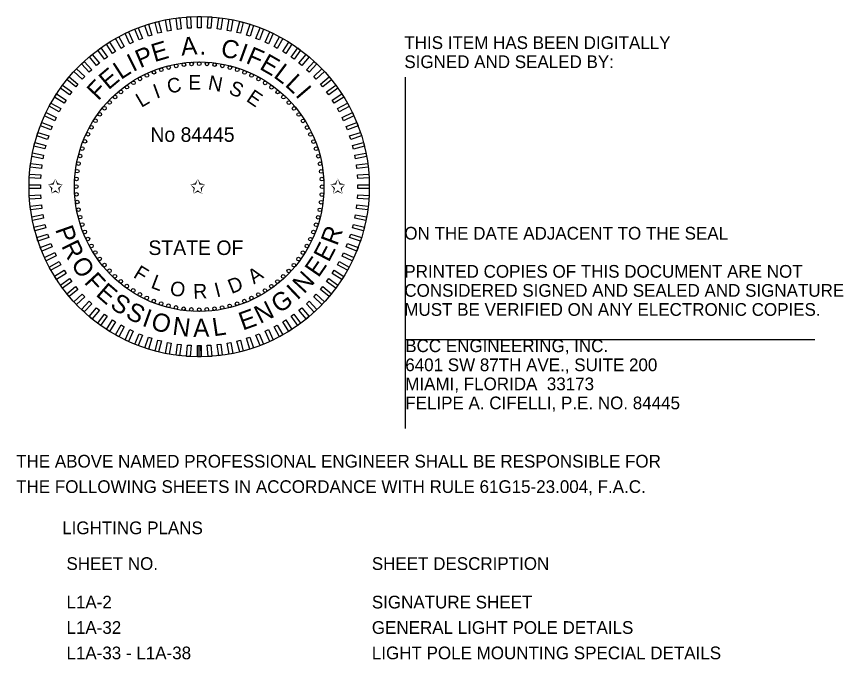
# Model space of a CAD drawing. Extents: x -811.2 to -795.1, y -2238.2 to -2204.
# Drawn here: x -802.539 to -797.983, y -2208.297 to -2204.755 of the extents above; entities that cross this region are included whole.
import ezdxf

# ---------------------------------------------------------------- set-up
doc = ezdxf.new("R2010")
doc.units = 0
for name, color, linetype in [('AdhocPoint_dp', 7, 'Continuous'), ('PlotBorder_dp', 7, 'Continuous'), ('TextMinor', 7, 'Continuous'), ('TextMisc', 7, 'Continuous'), ('TextShtNo', 7, 'Continuous')]:
    doc.layers.add(name, color=color, linetype=linetype)

msp = doc.modelspace()

# ---------------------------------------------------------------- linework, layer by layer
at = {"layer": 'AdhocPoint_dp'}
for p, q in [((-800.3974, -2205.0892), (-800.3974, -2207.0239)), ((-800.3974, -2206.5339), (-798.1407, -2206.5339))]:
    msp.add_line(p, q, dxfattribs=at)
at = {"layer": 'TextMinor'}
for radius in [0.9375, 0.6875]:
    msp.add_circle((-801.5329, -2205.6926), radius, dxfattribs=at)
at = {"layer": 'TextShtNo'}
for p, q in [((-801.5429, -2206.6301), (-801.5431, -2206.5676)), ((-801.5329, -2206.6301), (-801.5331, -2206.5676)), ((-801.5229, -2206.6301), (-801.5231, -2206.5676))]:
    msp.add_line(p, q, dxfattribs=at)
for points in [[(-801.7407, -2204.8425), (-801.7602, -2204.8475), (-801.7758, -2204.7871), (-801.7562, -2204.782)], [(-801.6869, -2204.8312), (-801.7067, -2204.8349), (-801.7184, -2204.7736), (-801.6986, -2204.7698)], [(-801.6325, -2204.8232), (-801.6525, -2204.8257), (-801.6603, -2204.7638), (-801.6403, -2204.7612)], [(-801.5777, -2204.8187), (-801.5978, -2204.8199), (-801.6018, -2204.7576), (-801.5816, -2204.7563)], [(-801.5227, -2204.8176), (-801.5429, -2204.8176), (-801.5429, -2204.7551), (-801.5227, -2204.7551)], [(-801.4678, -2204.8199), (-801.488, -2204.8187), (-801.484, -2204.7563), (-801.4639, -2204.7576)], [(-801.4131, -2204.8257), (-801.4332, -2204.8232), (-801.4254, -2204.7613), (-801.4053, -2204.7638)], [(-801.359, -2204.835), (-801.3788, -2204.8312), (-801.3671, -2204.7699), (-801.3473, -2204.7736)], [(-801.3054, -2204.8476), (-801.325, -2204.8426), (-801.3095, -2204.7821), (-801.2899, -2204.7871)], [(-801.8456, -2204.8753), (-801.8643, -2204.8827), (-801.8873, -2204.8246), (-801.8686, -2204.8172)], [(-801.7936, -2204.8572), (-801.8128, -2204.8635), (-801.8321, -2204.8041), (-801.8129, -2204.7979)], [(-801.2528, -2204.8635), (-801.272, -2204.8573), (-801.2527, -2204.7979), (-801.2335, -2204.8042)], [(-801.2013, -2204.8828), (-801.2201, -2204.8753), (-801.1971, -2204.8173), (-801.1783, -2204.8247)], [(-801.9455, -2204.9209), (-801.9632, -2204.9306), (-801.9933, -2204.8759), (-801.9756, -2204.8662)], [(-801.8963, -2204.8965), (-801.9145, -2204.9051), (-801.9411, -2204.8486), (-801.9229, -2204.84)], [(-801.1511, -2204.9052), (-801.1694, -2204.8966), (-801.1428, -2204.8401), (-801.1246, -2204.8487)], [(-801.1025, -2204.9307), (-801.1201, -2204.921), (-801.0901, -2204.8663), (-801.0724, -2204.876)], [(-802.039, -2204.9787), (-802.0553, -2204.9906), (-802.092, -2204.94), (-802.0757, -2204.9282)], [(-801.9932, -2204.9483), (-802.0102, -2204.9591), (-802.0437, -2204.9064), (-802.0266, -2204.8956)], [(-801.0555, -2204.9592), (-801.0725, -2204.9484), (-801.039, -2204.8957), (-801.022, -2204.9065)], [(-801.0104, -2204.9907), (-801.0267, -2204.9788), (-800.99, -2204.9283), (-800.9737, -2204.9402)], [(-802.0828, -2205.0119), (-802.0984, -2205.0247), (-802.1382, -2204.9766), (-802.1226, -2204.9638)], [(-800.9673, -2205.0249), (-800.9829, -2205.012), (-800.9431, -2204.9639), (-800.9275, -2204.9768)], [(-802.1245, -2205.0478), (-802.1392, -2205.0616), (-802.182, -2205.0161), (-802.1672, -2205.0022)], [(-800.9265, -2205.0617), (-800.9412, -2205.0479), (-800.8985, -2205.0024), (-800.8838, -2205.0162)], [(-802.1638, -2205.0862), (-802.1776, -2205.1009), (-802.2232, -2205.0581), (-802.2093, -2205.0434)], [(-800.8881, -2205.101), (-800.9019, -2205.0863), (-800.8564, -2205.0436), (-800.8426, -2205.0583)], [(-802.2007, -2205.127), (-802.2135, -2205.1425), (-802.2616, -2205.1027), (-802.2488, -2205.0872)], [(-800.8522, -2205.1427), (-800.8651, -2205.1271), (-800.817, -2205.0873), (-800.8041, -2205.1029)], [(-802.2349, -2205.17), (-802.2467, -2205.1864), (-802.2972, -2205.1497), (-802.2854, -2205.1333)], [(-800.819, -2205.1865), (-800.8309, -2205.1702), (-800.7804, -2205.1335), (-800.7685, -2205.1498)], [(-802.2663, -2205.2151), (-802.2771, -2205.2322), (-802.3298, -2205.1987), (-802.319, -2205.1817)], [(-800.7887, -2205.2323), (-800.7995, -2205.2153), (-800.7468, -2205.1818), (-800.7359, -2205.1989)], [(-802.2948, -2205.2621), (-802.3045, -2205.2798), (-802.3593, -2205.2497), (-802.3495, -2205.232)], [(-800.7612, -2205.28), (-800.7709, -2205.2623), (-800.7162, -2205.2322), (-800.7065, -2205.2499)], [(-802.3203, -2205.3108), (-802.3289, -2205.3291), (-802.3854, -2205.3025), (-802.3768, -2205.2842)], [(-800.7368, -2205.3292), (-800.7454, -2205.311), (-800.6889, -2205.2844), (-800.6803, -2205.3027)], [(-802.3428, -2205.361), (-802.3502, -2205.3798), (-802.4082, -2205.3568), (-802.4008, -2205.338)], [(-800.7156, -2205.3799), (-800.723, -2205.3612), (-800.665, -2205.3382), (-800.6575, -2205.357)], [(-802.362, -2205.4125), (-802.3682, -2205.4317), (-802.4276, -2205.4124), (-802.4214, -2205.3932)], [(-800.6976, -2205.4319), (-800.7038, -2205.4127), (-800.6444, -2205.3934), (-800.6382, -2205.4126)], [(-802.3779, -2205.4651), (-802.383, -2205.4847), (-802.4434, -2205.4691), (-802.4384, -2205.4496)], [(-800.6829, -2205.4849), (-800.6879, -2205.4653), (-800.6274, -2205.4498), (-800.6224, -2205.4693)], [(-802.3905, -2205.5186), (-802.3943, -2205.5385), (-802.4557, -2205.5268), (-802.4519, -2205.5069)], [(-800.6715, -2205.5386), (-800.6753, -2205.5188), (-800.6139, -2205.5071), (-800.6102, -2205.5269)], [(-802.3998, -2205.5728), (-802.4023, -2205.5928), (-802.4643, -2205.585), (-802.4617, -2205.565)], [(-800.6635, -2205.593), (-800.666, -2205.573), (-800.6041, -2205.5652), (-800.6016, -2205.5852)], [(-802.4056, -2205.6275), (-802.4069, -2205.6476), (-802.4692, -2205.6437), (-802.4679, -2205.6236)], [(-800.659, -2205.6478), (-800.6603, -2205.6277), (-800.5979, -2205.6238), (-800.5967, -2205.6439)], [(-802.408, -2205.6824), (-802.408, -2205.7026), (-802.4704, -2205.7026), (-802.4704, -2205.6824)], [(-800.6579, -2205.7028), (-800.6579, -2205.6826), (-800.5955, -2205.6826), (-800.5955, -2205.7028)], [(-802.4069, -2205.7374), (-802.4056, -2205.7575), (-802.4679, -2205.7614), (-802.4692, -2205.7413)], [(-800.6603, -2205.7577), (-800.659, -2205.7376), (-800.5967, -2205.7415), (-800.5979, -2205.7616)], [(-802.4023, -2205.7922), (-802.3998, -2205.8122), (-802.4618, -2205.82), (-802.4643, -2205.8)], [(-800.6661, -2205.8124), (-800.6635, -2205.7923), (-800.6016, -2205.8002), (-800.6041, -2205.8202)], [(-802.3944, -2205.8466), (-802.3906, -2205.8664), (-802.4519, -2205.8781), (-802.4557, -2205.8583)], [(-800.6753, -2205.8666), (-800.6715, -2205.8467), (-800.6102, -2205.8584), (-800.614, -2205.8783)], [(-802.383, -2205.9003), (-802.378, -2205.9199), (-802.4385, -2205.9354), (-802.4435, -2205.9159)], [(-800.6879, -2205.9201), (-800.6829, -2205.9005), (-800.6224, -2205.916), (-800.6274, -2205.9356)], [(-802.3683, -2205.9533), (-802.362, -2205.9725), (-802.4214, -2205.9918), (-802.4277, -2205.9726)], [(-800.7039, -2205.9727), (-800.6976, -2205.9535), (-800.6382, -2205.9728), (-800.6445, -2205.992)], [(-802.3503, -2206.0052), (-802.3428, -2206.024), (-802.4009, -2206.047), (-802.4083, -2206.0282)], [(-800.7231, -2206.0242), (-800.7157, -2206.0054), (-800.6576, -2206.0284), (-800.665, -2206.0472)], [(-802.329, -2206.0559), (-802.3204, -2206.0742), (-802.3769, -2206.1008), (-802.3855, -2206.0825)], [(-800.7455, -2206.0744), (-800.7369, -2206.0561), (-800.6804, -2206.0827), (-800.689, -2206.101)], [(-802.3046, -2206.1052), (-802.2949, -2206.1229), (-802.3496, -2206.153), (-802.3593, -2206.1353)], [(-800.771, -2206.1231), (-800.7613, -2206.1054), (-800.7066, -2206.1355), (-800.7163, -2206.1532)], [(-802.2772, -2206.1529), (-802.2664, -2206.1699), (-802.3191, -2206.2034), (-802.3299, -2206.1863)], [(-800.7996, -2206.1701), (-800.7888, -2206.153), (-800.736, -2206.1865), (-800.7469, -2206.2035)], [(-802.2468, -2206.1987), (-802.235, -2206.215), (-802.2855, -2206.2517), (-802.2973, -2206.2354)], [(-800.831, -2206.2152), (-800.8191, -2206.1988), (-800.7686, -2206.2355), (-800.7805, -2206.2519)], [(-802.2136, -2206.2425), (-802.2008, -2206.2581), (-802.2489, -2206.2979), (-802.2618, -2206.2823)], [(-800.8652, -2206.2582), (-800.8523, -2206.2427), (-800.8042, -2206.2825), (-800.8171, -2206.298)], [(-802.1778, -2206.2842), (-802.1639, -2206.2989), (-802.2095, -2206.3416), (-802.2233, -2206.3269)], [(-800.902, -2206.299), (-800.8882, -2206.2843), (-800.8427, -2206.327), (-800.8565, -2206.3418)], [(-802.1394, -2206.3235), (-802.1246, -2206.3373), (-802.1674, -2206.3828), (-802.1821, -2206.369)], [(-800.9414, -2206.3374), (-800.9266, -2206.3236), (-800.8839, -2206.3691), (-800.8986, -2206.383)], [(-802.0985, -2206.3603), (-802.083, -2206.3732), (-802.1228, -2206.4213), (-802.1383, -2206.4084)], [(-800.983, -2206.3733), (-800.9675, -2206.3604), (-800.9277, -2206.4086), (-800.9432, -2206.4214)], [(-802.0555, -2206.3945), (-802.0392, -2206.4064), (-802.0759, -2206.4569), (-802.0922, -2206.445)], [(-802.0104, -2206.426), (-801.9933, -2206.4368), (-802.0268, -2206.4895), (-802.0438, -2206.4787)], [(-801.0727, -2206.4369), (-801.0556, -2206.4261), (-801.0222, -2206.4788), (-801.0392, -2206.4896)], [(-801.0268, -2206.4065), (-801.0105, -2206.3946), (-800.9738, -2206.4451), (-800.9901, -2206.457)], [(-801.9634, -2206.4545), (-801.9457, -2206.4642), (-801.9758, -2206.5189), (-801.9935, -2206.5092)], [(-801.1203, -2206.4643), (-801.1026, -2206.4546), (-801.0725, -2206.5093), (-801.0902, -2206.519)], [(-801.9147, -2206.48), (-801.8964, -2206.4886), (-801.923, -2206.5451), (-801.9413, -2206.5365)], [(-801.8645, -2206.5024), (-801.8457, -2206.5099), (-801.8687, -2206.5679), (-801.8875, -2206.5605)], [(-801.813, -2206.5217), (-801.7938, -2206.5279), (-801.8131, -2206.5873), (-801.8323, -2206.581)], [(-801.2722, -2206.5279), (-801.253, -2206.5217), (-801.2337, -2206.5811), (-801.2529, -2206.5873)], [(-801.2203, -2206.5099), (-801.2015, -2206.5025), (-801.1785, -2206.5606), (-801.1973, -2206.568)], [(-801.1696, -2206.4887), (-801.1513, -2206.4801), (-801.1247, -2206.5366), (-801.143, -2206.5452)], [(-801.7604, -2206.5376), (-801.7409, -2206.5426), (-801.7564, -2206.6031), (-801.7759, -2206.5981)], [(-801.7069, -2206.5502), (-801.6871, -2206.554), (-801.6988, -2206.6153), (-801.7186, -2206.6116)], [(-801.6527, -2206.5594), (-801.6327, -2206.562), (-801.6405, -2206.6239), (-801.6605, -2206.6214)], [(-801.598, -2206.5653), (-801.5779, -2206.5665), (-801.5818, -2206.6288), (-801.602, -2206.6276)], [(-801.5431, -2206.5676), (-801.5229, -2206.5676), (-801.5229, -2206.6301), (-801.5431, -2206.6301)], [(-801.4881, -2206.5665), (-801.468, -2206.5653), (-801.4641, -2206.6276), (-801.4842, -2206.6289)], [(-801.4334, -2206.562), (-801.4133, -2206.5595), (-801.4055, -2206.6214), (-801.4255, -2206.624)], [(-801.379, -2206.554), (-801.3591, -2206.5503), (-801.3474, -2206.6116), (-801.3673, -2206.6154)], [(-801.3252, -2206.5427), (-801.3056, -2206.5376), (-801.2901, -2206.5981), (-801.3097, -2206.6031)]]:
    msp.add_lwpolyline(points, close=True, dxfattribs=at)
for centre in [(-801.6593, -2205.027), (-801.6173, -2205.0204), (-801.5749, -2205.0164), (-801.5324, -2205.0151), (-801.4898, -2205.0165), (-801.4475, -2205.0205), (-801.4054, -2205.0272), (-801.7818, -2205.0625), (-801.7417, -2205.0481), (-801.7009, -2205.0363), (-801.3639, -2205.0366), (-801.323, -2205.0485), (-801.283, -2205.0629), (-801.8955, -2205.1203), (-801.8588, -2205.0987), (-801.8209, -2205.0794), (-801.244, -2205.0798), (-801.2061, -2205.0992), (-801.1694, -2205.1209), (-801.9307, -2205.1442), (-801.1343, -2205.1448), (-801.9963, -2205.1984), (-801.9643, -2205.1702), (-801.1007, -2205.171), (-801.0688, -2205.1991), (-802.0264, -2205.2284), (-801.0387, -2205.2292), (-802.0807, -2205.2939), (-802.0546, -2205.2603), (-801.0106, -2205.2612), (-800.9845, -2205.2948), (-802.1046, -2205.3291), (-800.9606, -2205.3301), (-802.1263, -2205.3657), (-800.939, -2205.3667), (-802.1457, -2205.4036), (-800.9197, -2205.4047), (-802.1771, -2205.4827), (-802.1626, -2205.4427), (-800.9028, -2205.4437), (-800.8884, -2205.4838), (-802.189, -2205.5236), (-800.8766, -2205.5247), (-802.1983, -2205.5651), (-800.8674, -2205.5662), (-802.205, -2205.6071), (-800.8607, -2205.6082), (-802.209, -2205.6495), (-800.8568, -2205.6506), (-802.2104, -2205.692), (-800.8555, -2205.6932), (-802.2091, -2205.7346), (-800.8568, -2205.7357), (-802.2051, -2205.7769), (-800.8609, -2205.7781), (-802.1985, -2205.819), (-800.8676, -2205.8201), (-802.1893, -2205.8605), (-800.8769, -2205.8616), (-802.1774, -2205.9014), (-802.163, -2205.9415), (-800.8888, -2205.9025), (-802.1462, -2205.9805), (-800.9202, -2205.9816), (-800.9032, -2205.9425), (-802.1269, -2206.0185), (-800.9395, -2206.0195), (-802.1052, -2206.0551), (-800.9612, -2206.0561), (-802.0813, -2206.0903), (-802.0553, -2206.124), (-800.9852, -2206.0913), (-802.0272, -2206.1559), (-801.0395, -2206.1568), (-801.0113, -2206.1249), (-801.9971, -2206.1861), (-801.9652, -2206.2142), (-801.1015, -2206.215), (-801.0696, -2206.1868), (-801.9316, -2206.2403), (-801.1352, -2206.241), (-801.8964, -2206.2643), (-801.8598, -2206.286), (-801.8219, -2206.3053), (-801.245, -2206.3058), (-801.207, -2206.2865), (-801.1704, -2206.2649), (-801.7828, -2206.3223), (-801.7428, -2206.3367), (-801.702, -2206.3486), (-801.365, -2206.3489), (-801.3241, -2206.3371), (-801.2841, -2206.3227), (-801.6604, -2206.358), (-801.6184, -2206.3647), (-801.576, -2206.3687), (-801.5329, -2206.3701), (-801.4909, -2206.3688), (-801.4486, -2206.3648), (-801.4065, -2206.3582)]:
    msp.add_circle(centre, 0.01, dxfattribs=at)

# ---------------------------------------------------------------- texts
at = {"layer": 'PlotBorder_dp'}
for s, p in [('THIS ITEM HAS BEEN DIGITALLY', (-800.4024, -2204.934)), ('SIGNED AND SEALED BY:', (-800.4024, -2205.039)), ('ON THE DATE ADJACENT TO THE SEAL', (-800.4024, -2205.984)), ('PRINTED COPIES OF THIS DOCUMENT ARE NOT ', (-800.4024, -2206.194)), ('CONSIDERED SIGNED AND SEALED AND SIGNATURE ', (-800.4024, -2206.299)), ('MUST BE VERIFIED ON ANY ELECTRONIC COPIES.', (-800.4024, -2206.404)), ('BCC ENGINEERING, INC.', (-800.3974, -2206.6039)), ('6401 SW 87TH AVE., SUITE 200', (-800.3974, -2206.7089)), ('MIAMI, FLORIDA  33173', (-800.3974, -2206.8139)), ('FELIPE A. CIFELLI, P.E. NO. 84445', (-800.3974, -2206.9189)), ('THE ABOVE NAMED PROFESSIONAL ENGINEER SHALL BE RESPONSIBLE FOR ', (-802.5415, -2207.24)), ('THE FOLLOWING SHEETS IN ACCORDANCE WITH RULE 61G15-23.004, F.A.C.', (-802.5415, -2207.38)), ('LIGHTING PLANS', (-802.2878, -2207.6071))]:
    msp.add_text(s, height=0.07, dxfattribs=at).set_placement(p)
at = {"layer": 'TextMisc'}
for s, p in [('SHEET NO.', (-802.2643, -2207.8041)), ('SHEET DESCRIPTION', (-800.5815, -2207.8041)), ('L1A-2', (-802.2643, -2208.0162)), ('SIGNATURE SHEET', (-800.5815, -2208.0162)), ('L1A-32', (-802.2643, -2208.1562)), ('GENERAL LIGHT POLE DETAILS', (-800.5815, -2208.1562)), ('L1A-33 - L1A-38', (-802.2643, -2208.2962)), ('LIGHT POLE MOUNTING SPECIAL DETAILS', (-800.5815, -2208.2962))]:
    msp.add_text(s, height=0.07, dxfattribs=at).set_placement(p)
at = {"layer": 'TextShtNo'}
for s, height, rotation, p in [('A', 0.1, 4.421, (-801.6298, -2204.9704)), ('C', 0.1, 347.7999, (-801.4192, -2204.9729)), ('P', 0.1, 23.2829, (-801.8581, -2205.0405)), ('E', 0.1, 16.5426, (-801.7793, -2205.0069)), ('I', 0.1, 340.0631, (-801.3234, -2204.9947)), ('F', 0.1, 336.5299, (-801.2807, -2205.009)), ('I', 0.1, 26.8161, (-801.8977, -2205.0618)), ('.', 0.1, 356.654, (-801.5313, -2204.9639)), ('E', 0.1, 330.0796, (-801.2055, -2205.0416)), ('L', 0.1, 33.0792, (-801.9643, -2205.1054)), ('L', 0.1, 323.0373, (-801.1282, -2205.0867)), ('E', 0.1, 40.1214, (-802.033, -2205.1627)), ('F', 0.1, 46.5718, (-802.0894, -2205.2222)), ('C', 0.08, 12.2025, (-801.7007, -2205.181)), ('E', 0.08, 0.4186, (-801.5926, -2205.1575)), ('N', 0.08, 349.2914, (-801.4883, -2205.1561)), ('L', 0.1, 316.7742, (-801.0645, -2205.1344)), ('I', 0.08, 20.0117, (-801.7686, -2205.2085)), ('S', 0.08, 337.0221, (-801.3753, -2205.1778)), ('E', 0.08, 325.8663, (-801.2786, -2205.218)), ('I', 0.1, 310.5111, (-801.0064, -2205.1889)), ('L', 0.08, 30.4021, (-801.8521, -2205.259)), ('P', 0.1, 289.4055, (-802.3276, -2205.9272)), ('R', 0.1, 69.5134, (-800.7727, -2206.0223)), ('R', 0.1, 296.1458, (-802.2946, -2206.0188)), ('E', 0.1, 62.4712, (-800.8189, -2206.113)), ('O', 0.1, 303.9671, (-802.2431, -2206.1194)), ('E', 0.1, 55.4289, (-800.8758, -2206.1974)), ('F', 0.08, 328.7241, (-801.901, -2206.1892)), ('A', 0.08, 34.4992, (-801.2311, -2206.232)), ('N', 0.1, 47.1788, (-800.9551, -2206.2864)), ('F', 0.1, 312.628, (-802.1708, -2206.2215)), ('L', 0.08, 339.2916, (-801.8037, -2206.2483)), ('D', 0.08, 22.0128, (-801.3549, -2206.2845)), ('E', 0.1, 319.0783, (-802.1073, -2206.2898)), ('O', 0.08, 349.6821, (-801.699, -2206.288)), ('R', 0.08, 2.3398, (-801.5645, -2206.3099)), ('I', 0.08, 14.2037, (-801.4369, -2206.3032)), ('I', 0.1, 43.6456, (-800.9928, -2206.3209)), ('S', 0.1, 326.1206, (-802.0297, -2206.3557)), ('G', 0.1, 35.1115, (-801.092, -2206.3941)), ('S', 0.1, 333.193, (-801.9443, -2206.4119)), ('N', 0.1, 26.8614, (-801.1972, -2206.4501)), ('I', 0.1, 340.2654, (-801.8526, -2206.457)), ('O', 0.1, 343.7986, (-801.8049, -2206.4753)), ('E', 0.1, 19.8191, (-801.2926, -2206.4856)), ('N', 0.1, 352.4595, (-801.6839, -2206.5073)), ('A', 0.1, 0.7097, (-801.5655, -2206.5206)), ('L', 0.1, 8.4767, (-801.4533, -2206.5174))]:
    msp.add_text(s, height=height, rotation=rotation, dxfattribs=at).set_placement(p)
for s, p in [('No 84445', (-801.8019, -2205.4454)), ('✩', (-802.3679, -2205.7305)), ('✩', (-801.5832, -2205.7305)), ('✩', (-800.8113, -2205.7305)), ('STATE OF', (-801.8126, -2206.0688))]:
    msp.add_text(s, height=0.08, dxfattribs=at).set_placement(p)

doc.saveas('drawing.dxf')
